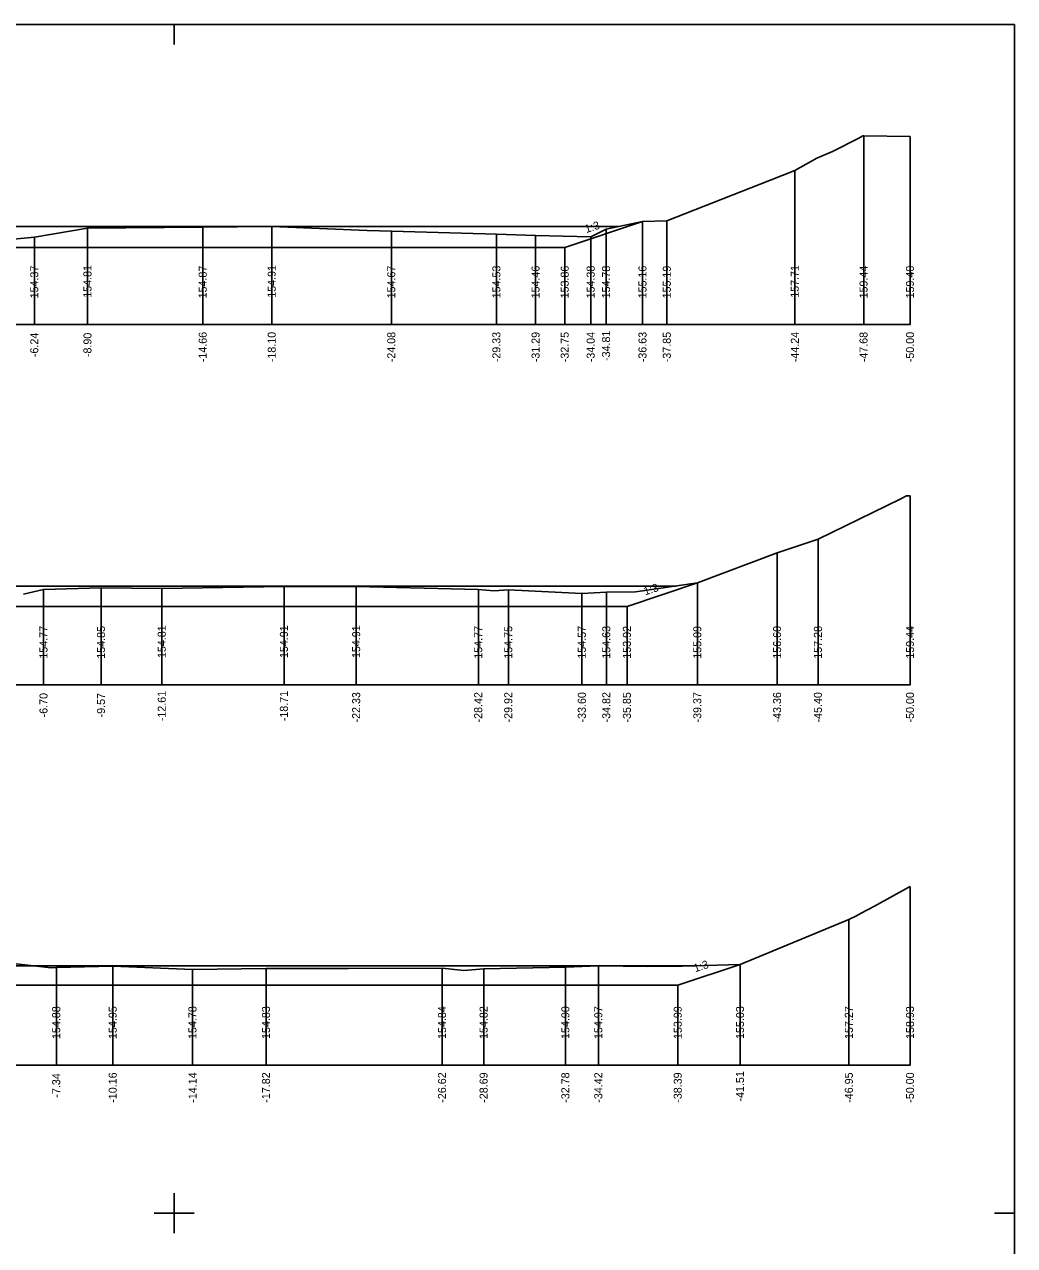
# Model space of a CAD drawing. Extents: x -582678 to -581845, y -1210354 to -1210235.
# Drawn here: x -582517 to -582467.5, y -1210296.3 to -1210235.3 of the extents above; entities that cross this region are included whole.
import ezdxf

# ---------------------------------------------------------------- set-up
doc = ezdxf.new("R2010")
doc.units = 0
for name, color, linetype in [('8', 7, 'Continuous'), ('_N_popis', 7, 'Continuous'), ('_N_tučná', 7, 'Continuous'), ('_rámeček', 7, 'Continuous'), ('_S_hladina', 7, 'Continuous'), ('_S_popis', 7, 'Continuous'), ('_S_tenká', 7, 'Continuous'), ('_S_velmi_tenká', 7, 'Continuous')]:
    doc.layers.add(name, color=color, linetype=linetype)

msp = doc.modelspace()

# ---------------------------------------------------------------- linework, layer by layer
at = {"layer": '_N_popis'}
for points in [[(-582486.089, -1210245.135), (-582486.089, -1210250.291), (-582486.089, -1210250.291), (-582486.089, -1210250.291)], [(-582489.976, -1210246.431), (-582489.976, -1210250.291), (-582489.976, -1210250.291), (-582489.976, -1210250.291)], [(-582483.351, -1210263.198), (-582483.351, -1210268.291), (-582483.351, -1210268.291), (-582483.351, -1210268.291)], [(-582486.869, -1210264.371), (-582486.869, -1210268.291), (-582486.869, -1210268.291), (-582486.869, -1210268.291)], [(-582481.217, -1210282.264), (-582481.217, -1210287.291), (-582481.217, -1210287.291), (-582481.217, -1210287.291)], [(-582484.328, -1210283.301), (-582484.328, -1210287.291), (-582484.328, -1210287.291), (-582484.328, -1210287.291)]]:
    msp.add_lwpolyline(points, dxfattribs=at)
at = {"layer": '_N_tučná'}
for p, q in [((-582486.089, -1210245.135), (-582489.976, -1210246.431)), ((-582483.351, -1210263.198), (-582486.869, -1210264.371)), ((-582481.217, -1210282.264), (-582484.328, -1210283.301))]:
    msp.add_line(p, q, dxfattribs=at)
for points in [[(-582489.976, -1210246.431), (-582548.281, -1210246.431)], [(-582486.869, -1210264.371), (-582551.445, -1210264.371)], [(-582484.328, -1210283.301), (-582539.78, -1210283.301)]]:
    msp.add_lwpolyline(points, dxfattribs=at)
at = {"layer": '_rámeček'}
for p, q in [((-582467.502, -1210235.291), (-582677.502, -1210235.291)), ((-582509.502, -1210235.291), (-582509.502, -1210236.291)), ((-582467.502, -1210354.091), (-582467.502, -1210235.291)), ((-582467.502, -1210235.291), (-582467.502, -1210236.291)), ((-582509.502, -1210293.691), (-582509.502, -1210295.691)), ((-582510.502, -1210294.691), (-582508.502, -1210294.691)), ((-582468.502, -1210294.691), (-582467.502, -1210294.691))]:
    msp.add_line(p, q, dxfattribs=at)
at = {"layer": '_S_hladina'}
msp.add_line((-582523.567, -1210282.321), (-582516.554, -1210282.321), dxfattribs=at)
for points in [[(-582552.213, -1210245.381), (-582487.268, -1210245.381)], [(-582555.2, -1210263.351), (-582484.431, -1210263.351)], [(-582516.554, -1210282.321), (-582483.407, -1210282.321)]]:
    msp.add_lwpolyline(points, dxfattribs=at)
at = {"layer": '_S_popis'}
msp.add_lwpolyline([(-582488.681, -1210245.907), (-582488.681, -1210250.291), (-582488.681, -1210250.291), (-582488.681, -1210250.291)], dxfattribs=at)
at = {"layer": '_S_tenká'}
for p, q in [((-582472.722, -1210250.291), (-582567.528, -1210250.291)), ((-582472.722, -1210268.291), (-582569.895, -1210268.291)), ((-582472.722, -1210287.291), (-582570.452, -1210287.291))]:
    msp.add_line(p, q, dxfattribs=at)
for points in [[(-582472.722, -1210240.892), (-582475.043, -1210240.85), (-582475.063, -1210240.851), (-582475.091, -1210240.858), (-582475.293, -1210240.976), (-582476.607, -1210241.642), (-582477.378, -1210241.965), (-582478.482, -1210242.582), (-582479.754, -1210243.089), (-582484.874, -1210245.103), (-582486.089, -1210245.135), (-582487.91, -1210245.515), (-582488.681, -1210245.907), (-582491.434, -1210245.829), (-582493.39, -1210245.763), (-582498.642, -1210245.626), (-582499.857, -1210245.593), (-582504.617, -1210245.38), (-582508.066, -1210245.421), (-582513.824, -1210245.478), (-582516.482, -1210245.92), (-582518.043, -1210246.078)], [(-582472.722, -1210258.846), (-582472.897, -1210258.851), (-582473.225, -1210259.011), (-582477.324, -1210261.007), (-582479.364, -1210261.691), (-582483.351, -1210263.198), (-582486.447, -1210263.636), (-582487.899, -1210263.66), (-582489.12, -1210263.716), (-582492.798, -1210263.539), (-582493.516, -1210263.599), (-582494.298, -1210263.523), (-582500.397, -1210263.38), (-582504.009, -1210263.379), (-582510.113, -1210263.479), (-582513.148, -1210263.436), (-582516.021, -1210263.52), (-582517.019, -1210263.764)], [(-582472.722, -1210278.364), (-582472.781, -1210278.397), (-582474.51, -1210279.351), (-582475.205, -1210279.719), (-582475.405, -1210279.827), (-582475.777, -1210280.016), (-582481.217, -1210282.264), (-582484.097, -1210282.339), (-582485.835, -1210282.364), (-582488.298, -1210282.319), (-582489.943, -1210282.393), (-582494.029, -1210282.472), (-582495.028, -1210282.558), (-582496.106, -1210282.45), (-582500.779, -1210282.465), (-582504.903, -1210282.46), (-582508.578, -1210282.509), (-582512.564, -1210282.336), (-582515.386, -1210282.41), (-582515.644, -1210282.426), (-582518.448, -1210282.103)]]:
    msp.add_lwpolyline(points, dxfattribs=at)
at = {"layer": '_S_velmi_tenká'}
for points in [[(-582475.043, -1210240.85), (-582475.043, -1210250.291), (-582475.043, -1210250.291), (-582475.043, -1210250.291)], [(-582472.722, -1210240.892), (-582472.722, -1210250.291), (-582472.722, -1210250.291), (-582472.722, -1210250.291)], [(-582478.482, -1210242.582), (-582478.482, -1210250.291), (-582478.482, -1210250.291), (-582478.482, -1210250.291)], [(-582513.824, -1210245.478), (-582513.824, -1210250.291), (-582513.824, -1210250.291), (-582513.824, -1210250.291)], [(-582508.066, -1210245.421), (-582508.066, -1210250.291), (-582508.066, -1210250.291), (-582508.066, -1210250.291)], [(-582504.617, -1210245.38), (-582504.617, -1210250.291), (-582504.617, -1210250.291), (-582504.617, -1210250.291)], [(-582484.874, -1210245.103), (-582484.874, -1210250.291), (-582484.874, -1210250.291), (-582484.874, -1210250.291)], [(-582516.482, -1210245.92), (-582516.482, -1210250.291), (-582516.482, -1210250.291), (-582516.482, -1210250.291)], [(-582498.642, -1210245.626), (-582498.642, -1210250.291), (-582498.642, -1210250.291), (-582498.642, -1210250.291)], [(-582493.39, -1210245.763), (-582493.39, -1210250.291), (-582493.39, -1210250.291), (-582493.39, -1210250.291)], [(-582491.434, -1210245.829), (-582491.434, -1210250.291), (-582491.434, -1210250.291), (-582491.434, -1210250.291)], [(-582487.91, -1210245.515), (-582487.91, -1210250.291), (-582487.91, -1210250.291), (-582487.91, -1210250.291)], [(-582472.722, -1210258.846), (-582472.722, -1210268.291), (-582472.722, -1210268.291), (-582472.722, -1210268.291)], [(-582477.324, -1210261.007), (-582477.324, -1210268.291), (-582477.324, -1210268.291), (-582477.324, -1210268.291)], [(-582479.364, -1210261.691), (-582479.364, -1210268.291), (-582479.364, -1210268.291), (-582479.364, -1210268.291)], [(-582516.021, -1210263.52), (-582516.021, -1210268.291), (-582516.021, -1210268.291), (-582516.021, -1210268.291)], [(-582513.148, -1210263.436), (-582513.148, -1210268.291), (-582513.148, -1210268.291), (-582513.148, -1210268.291)], [(-582510.113, -1210263.479), (-582510.113, -1210268.291), (-582510.113, -1210268.291), (-582510.113, -1210268.291)], [(-582504.009, -1210263.379), (-582504.009, -1210268.291), (-582504.009, -1210268.291), (-582504.009, -1210268.291)], [(-582500.397, -1210263.38), (-582500.397, -1210268.291), (-582500.397, -1210268.291), (-582500.397, -1210268.291)], [(-582494.298, -1210263.523), (-582494.298, -1210268.291), (-582494.298, -1210268.291), (-582494.298, -1210268.291)], [(-582492.798, -1210263.539), (-582492.798, -1210268.291), (-582492.798, -1210268.291), (-582492.798, -1210268.291)], [(-582489.12, -1210263.716), (-582489.12, -1210268.291), (-582489.12, -1210268.291), (-582489.12, -1210268.291)], [(-582487.899, -1210263.66), (-582487.899, -1210268.291), (-582487.899, -1210268.291), (-582487.899, -1210268.291)], [(-582472.722, -1210278.364), (-582472.722, -1210287.291), (-582472.722, -1210287.291), (-582472.722, -1210287.291)], [(-582475.777, -1210280.016), (-582475.777, -1210287.291), (-582475.777, -1210287.291), (-582475.777, -1210287.291)], [(-582515.386, -1210282.41), (-582515.386, -1210287.291), (-582515.386, -1210287.291), (-582515.386, -1210287.291)], [(-582512.564, -1210282.336), (-582512.564, -1210287.291), (-582512.564, -1210287.291), (-582512.564, -1210287.291)], [(-582508.578, -1210282.509), (-582508.578, -1210287.291), (-582508.578, -1210287.291), (-582508.578, -1210287.291)], [(-582504.903, -1210282.46), (-582504.903, -1210287.291), (-582504.903, -1210287.291), (-582504.903, -1210287.291)], [(-582496.106, -1210282.45), (-582496.106, -1210287.291), (-582496.106, -1210287.291), (-582496.106, -1210287.291)], [(-582494.029, -1210282.472), (-582494.029, -1210287.291), (-582494.029, -1210287.291), (-582494.029, -1210287.291)], [(-582489.943, -1210282.393), (-582489.943, -1210287.291), (-582489.943, -1210287.291), (-582489.943, -1210287.291)], [(-582488.298, -1210282.319), (-582488.298, -1210287.291), (-582488.298, -1210287.291), (-582488.298, -1210287.291)]]:
    msp.add_lwpolyline(points, dxfattribs=at)

# ---------------------------------------------------------------- texts
at = {"layer": '8'}
for p in [(-582472.722, -1210250.291), (-582472.722, -1210268.291)]:
    msp.add_text('-', height=6.000000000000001e-11, dxfattribs=at).set_placement(p)
at = {"layer": '_N_popis'}
for s, rotation, p in [('1:3', 18.43495, (-582488.9, -1210245.718)), ('153.86', 90, (-582489.783, -1210248.981)), ('155.16', 90, (-582485.896, -1210248.981)), ('-32.75', 90, (-582489.783, -1210252.171)), ('-36.63', 90, (-582485.896, -1210252.169)), ('1:3', 18.43495, (-582485.96, -1210263.822)), ('153.92', 90, (-582486.675, -1210266.98)), ('155.09', 90, (-582483.158, -1210266.982)), ('-35.85', 90, (-582486.675, -1210270.171)), ('-39.37', 90, (-582483.158, -1210270.169)), ('1:3', 18.43495, (-582483.463, -1210282.652)), ('153.99', 90, (-582484.135, -1210285.982)), ('155.03', 90, (-582481.024, -1210285.981)), ('-38.39', 90, (-582484.135, -1210289.17)), ('-41.51', 90, (-582481.024, -1210289.106))]:
    msp.add_text(s, height=0.4, rotation=rotation, dxfattribs=at).set_placement(p)
at = {"layer": '_S_popis'}
for s, p in [('154.37', (-582516.289, -1210248.981)), ('154.81', (-582513.631, -1210248.949)), ('154.87', (-582507.873, -1210248.981)), ('154.91', (-582504.424, -1210248.949)), ('154.67', (-582498.449, -1210248.981)), ('154.53', (-582493.197, -1210248.981)), ('154.46', (-582491.24, -1210248.981)), ('154.38', (-582488.487, -1210248.982)), ('154.78', (-582487.717, -1210248.982)), ('155.19', (-582484.681, -1210248.982)), ('157.71', (-582478.289, -1210248.949)), ('159.44', (-582474.85, -1210248.981)), ('159.40', (-582472.529, -1210248.981)), ('-6.24', (-582516.289, -1210251.913)), ('-8.90', (-582513.631, -1210251.913)), ('-14.66', (-582507.873, -1210252.169)), ('-18.10', (-582504.424, -1210252.168)), ('-24.08', (-582498.449, -1210252.17)), ('-29.33', (-582493.197, -1210252.169)), ('-31.29', (-582491.24, -1210252.17)), ('-34.04', (-582488.487, -1210252.168)), ('-34.81', (-582487.717, -1210252.106)), ('-37.85', (-582484.681, -1210252.171)), ('-44.24', (-582478.282, -1210252.168)), ('-47.68', (-582474.85, -1210252.17)), ('-50.00', (-582472.529, -1210252.168)), ('154.77', (-582515.828, -1210266.981)), ('154.85', (-582512.955, -1210266.982)), ('154.81', (-582509.919, -1210266.949)), ('154.91', (-582503.816, -1210266.949)), ('154.91', (-582500.204, -1210266.949)), ('154.77', (-582494.105, -1210266.981)), ('154.75', (-582492.604, -1210266.982)), ('154.57', (-582488.927, -1210266.981)), ('154.63', (-582487.706, -1210266.981)), ('156.60', (-582479.171, -1210266.981)), ('157.28', (-582477.131, -1210266.982)), ('159.44', (-582472.529, -1210266.981)), ('-12.61', (-582509.919, -1210270.106)), ('-18.71', (-582503.816, -1210270.106)), ('-22.33', (-582500.204, -1210270.169)), ('-28.42', (-582494.105, -1210270.166)), ('-29.92', (-582492.604, -1210270.166)), ('-33.60', (-582488.927, -1210270.168)), ('-34.82', (-582487.706, -1210270.166)), ('-43.36', (-582479.171, -1210270.169)), ('-45.40', (-582477.131, -1210270.168)), ('-50.00', (-582472.529, -1210270.168)), ('-6.70', (-582515.828, -1210269.913)), ('-9.57', (-582512.955, -1210269.914)), ('154.88', (-582515.193, -1210285.982)), ('154.95', (-582512.371, -1210285.982)), ('154.78', (-582508.385, -1210285.982)), ('154.83', (-582504.71, -1210285.981)), ('154.84', (-582495.913, -1210285.981)), ('154.82', (-582493.836, -1210285.98)), ('154.90', (-582489.75, -1210285.981)), ('154.97', (-582488.105, -1210285.981)), ('157.27', (-582475.584, -1210285.981)), ('158.93', (-582472.529, -1210285.981)), ('-7.34', (-582515.193, -1210288.913)), ('-10.16', (-582512.371, -1210289.169)), ('-14.14', (-582508.378, -1210289.168)), ('-17.82', (-582504.71, -1210289.166)), ('-26.62', (-582495.913, -1210289.166)), ('-28.69', (-582493.836, -1210289.17)), ('-32.78', (-582489.75, -1210289.17)), ('-34.42', (-582488.105, -1210289.166)), ('-46.95', (-582475.584, -1210289.171)), ('-50.00', (-582472.529, -1210289.168))]:
    msp.add_text(s, height=0.4, rotation=90, dxfattribs=at).set_placement(p)

doc.saveas('drawing.dxf')
